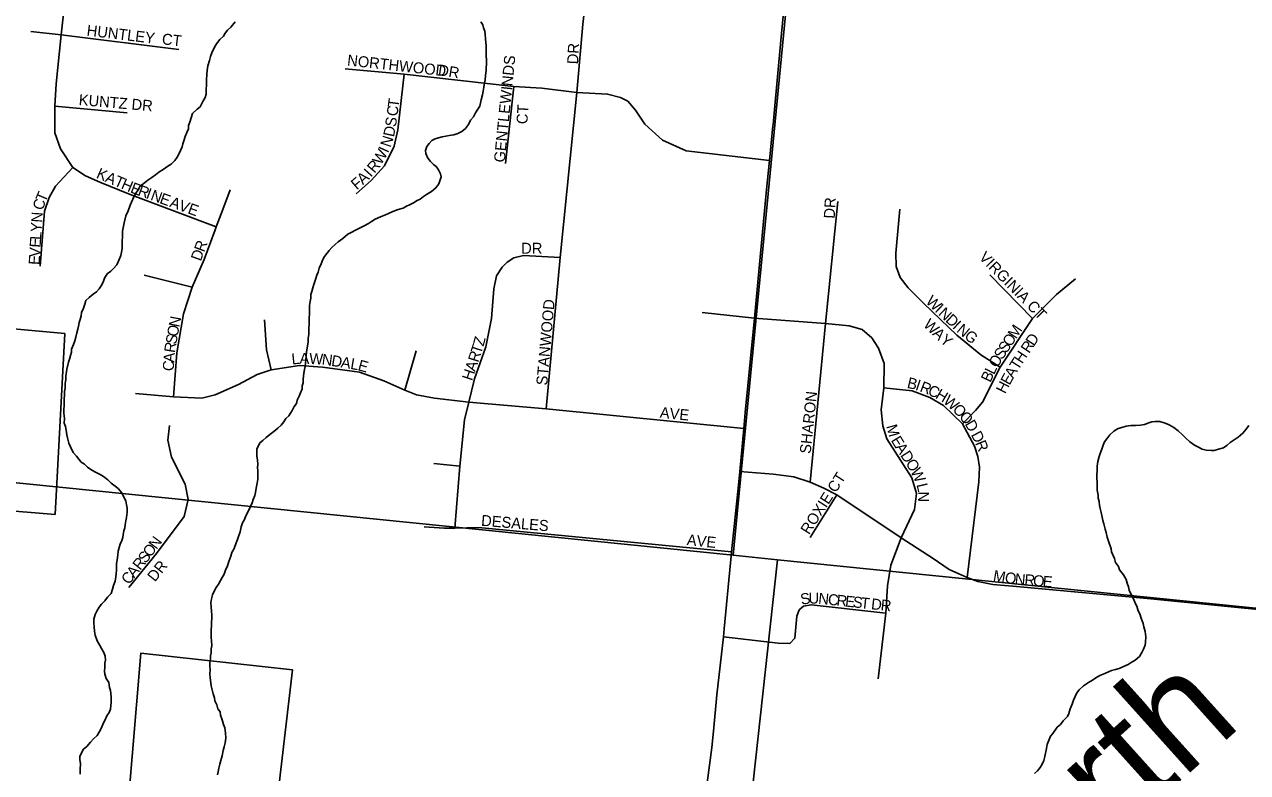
# Model space of a CAD drawing. Extents: x 0 to 1064, y 0 to 440.
# Drawn here: x 235.6 to 252.5, y 251.21 to 261.54 of the extents above; entities that cross this region are included whole.
import ezdxf

# ---------------------------------------------------------------- set-up
doc = ezdxf.new("R2010")
doc.units = 0
for name, color, linetype in [('GM_X_City_Street', 7, 'Continuous'), ('GM_X_City_Street_Text', 7, 'Continuous'), ('GM_X_Corporation', 7, 'Continuous'), ('GM_X_Minor_River', 7, 'Continuous'), ('GM_X_Minor_River_Text', 7, 'Continuous'), ('GM_X_Section', 7, 'Continuous'), ('GM_X_State_Route', 7, 'Continuous')]:
    doc.layers.add(name, color=color, linetype=linetype)

msp = doc.modelspace()

# ---------------------------------------------------------------- linework, layer by layer
at = {"layer": 'GM_X_City_Street'}
for points in [[(238.235, 258.707), (238.25, 258.748), (237.06, 259.196), (236.641, 259.365), (236.441, 259.452), (236.269, 259.569), (236.095, 259.825), (236.019, 260.045), (236.019, 260.414), (236.039, 260.725), (236.108, 261.4), (236.204, 262.278), (236.297, 263.152), (236.367, 264.019), (236.44, 264.965)], [(242.808, 256.231), (243.002, 258.326), (243.231, 260.605), (243.316, 261.548), (243.392, 262.217)], [(235.689, 261.448), (236.108, 261.4), (237.731, 261.2)], [(240.029, 260.931), (240.846, 260.859), (242.363, 260.688), (242.747, 260.662), (243.231, 260.605), (243.656, 260.583), (243.834, 260.536), (243.934, 260.484), (244.042, 260.358), (244.171, 260.165), (244.416, 259.943), (244.743, 259.798), (245.894, 259.666)], [(240.181, 259.202), (240.39, 259.387), (240.572, 259.589), (240.708, 259.863), (240.757, 260.086), (240.846, 260.859)], [(242.244, 259.623), (242.363, 260.688)], [(236.019, 260.414), (237.018, 260.325)], [(235.817, 258.206), (235.878, 258.963), (235.939, 259.152), (236.03, 259.309), (236.269, 259.569)], [(238.25, 258.748), (238.341, 258.987), (238.443, 259.259)], [(246.456, 255.22), (246.666, 257.413), (246.839, 259.097)], [(249.081, 256.809), (248.814, 256.979), (248.48, 257.251), (248.027, 257.686), (247.808, 257.907), (247.699, 258.046), (247.645, 258.2), (247.639, 258.383), (247.694, 258.99)], [(237.66, 256.398), (237.703, 257.006), (237.798, 257.545), (237.916, 257.914), (238.081, 258.296), (238.235, 258.707)], [(241.547, 254.586), (241.616, 255.442), (241.681, 256.081), (241.74, 256.326), (241.816, 256.649), (241.974, 257.088), (242.054, 257.482), (242.085, 257.89), (242.122, 258.072), (242.198, 258.191), (242.27, 258.261), (242.359, 258.321), (242.493, 258.35), (243.002, 258.326)], [(237.252, 258.08), (237.916, 257.914)], [(249.526, 257.48), (248.936, 258.085)], [(248.558, 256.027), (248.74, 256.209), (248.838, 256.326), (249.081, 256.809), (249.526, 257.48), (249.858, 257.814), (250.122, 258.027)], [(245.74, 257.482), (245.686, 257.486), (244.961, 257.563)], [(239.01, 256.771), (238.945, 257.049), (238.915, 257.464)], [(247.394, 252.503), (247.499, 253.409), (247.526, 253.785), (247.571, 254.074), (247.712, 254.449), (247.898, 254.844), (247.923, 255.064), (247.862, 255.278), (247.513, 255.82), (247.461, 256), (247.436, 256.22), (247.473, 256.524), (247.479, 256.86), (247.398, 257.069), (247.309, 257.213), (247.172, 257.329), (246.992, 257.38), (246.666, 257.413), (245.74, 257.482)], [(240.855, 256.491), (241.011, 257.036)], [(237.66, 256.398), (238.05, 256.38), (238.234, 256.425), (238.559, 256.571), (238.813, 256.706), (239.01, 256.771), (239.399, 256.832), (239.719, 256.81), (240.227, 256.739), (240.566, 256.622), (240.855, 256.491), (241.015, 256.428), (241.264, 256.381), (241.74, 256.326), (242.808, 256.231), (245.537, 255.959)], [(237.133, 256.446), (237.66, 256.398)], [(248.625, 253.903), (248.785, 255.223), (248.794, 255.429), (248.77, 255.575), (248.728, 255.716), (248.558, 256.027), (248.298, 256.278), (248.111, 256.391), (247.864, 256.48), (247.473, 256.524)], [(237.043, 253.765), (237.426, 254.234), (237.804, 254.743), (237.86, 254.981), (237.821, 255.194), (237.63, 255.564), (237.582, 255.798), (237.604, 256.002)], [(241.256, 255.477), (241.616, 255.442)], [(245.484, 255.365), (245.944, 255.328), (246.228, 255.291), (246.456, 255.22), (246.643, 255.137), (246.825, 255.046), (247.712, 254.449), (248.155, 254.163), (248.374, 254.011), (248.625, 253.903), (248.773, 253.849), (248.981, 253.805), (249.198, 253.786)], [(246.455, 254.455), (246.825, 255.046)], [(241.122, 254.601), (241.398, 254.584), (241.547, 254.586), (241.873, 254.595), (245.369, 254.259)], [(249.198, 253.786), (249.256, 253.781), (251.164, 253.606), (252.923, 253.434), (254.033, 253.283), (257.105, 252.989), (258.422, 252.857), (259.76, 252.73)], [(245.256, 253.082), (246.011, 252.993), (246.176, 252.99), (246.244, 253.064), (246.27, 253.37), (246.302, 253.455), (246.365, 253.507), (246.467, 253.525), (247.499, 253.409)]]:
    msp.add_lwpolyline(points, dxfattribs=at)
at = {"layer": 'GM_X_Corporation'}
msp.add_lwpolyline([(229.017, 255.354), (236.023, 254.775), (236.156, 257.273), (234.842, 257.395)], dxfattribs=at)
msp.add_lwpolyline([(236.902, 249.23), (239.076, 248.99), (239.161, 249.674), (238.956, 249.674), (239.304, 252.625), (237.209, 252.859)], close=True, dxfattribs=at)
at = {"layer": 'GM_X_Minor_River'}
for points in [[(236.222, 256.918), (236.236, 256.972), (236.249, 257.014), (236.251, 257.057), (236.277, 257.123), (236.297, 257.171), (236.311, 257.225), (236.325, 257.285), (236.339, 257.333), (236.346, 257.376), (236.354, 257.424), (236.368, 257.466), (236.382, 257.52), (236.389, 257.563), (236.415, 257.623), (236.435, 257.677), (236.449, 257.731), (236.493, 257.772), (236.55, 257.819), (236.593, 257.848), (236.631, 257.889), (236.657, 257.931), (236.689, 257.984), (236.703, 258.039), (236.742, 258.098), (236.791, 258.133), (236.829, 258.174), (236.874, 258.222), (236.906, 258.294), (236.933, 258.353), (236.94, 258.396), (236.948, 258.45), (236.95, 258.499), (236.951, 258.547), (236.954, 258.62), (236.956, 258.687), (236.963, 258.735), (236.978, 258.801), (236.999, 258.898), (237.032, 258.97), (237.059, 259.048), (237.098, 259.132), (237.131, 259.197), (237.169, 259.257), (237.195, 259.305), (237.258, 259.357), (237.302, 259.393), (237.358, 259.427), (237.408, 259.468), (237.458, 259.503), (237.514, 259.538), (237.582, 259.584), (237.626, 259.613), (237.676, 259.666), (237.708, 259.708), (237.734, 259.75), (237.754, 259.804), (237.78, 259.851), (237.787, 259.894), (237.801, 259.936), (237.821, 259.996), (237.841, 260.05), (237.867, 260.104), (237.868, 260.146), (237.882, 260.194), (237.902, 260.254), (237.923, 260.315), (237.986, 260.373), (238.029, 260.408), (238.062, 260.48), (238.094, 260.534), (238.108, 260.582), (238.11, 260.631), (238.113, 260.722), (238.115, 260.776), (238.117, 260.855), (238.125, 260.909), (238.133, 260.97), (238.154, 261.048), (238.168, 261.102), (238.188, 261.15), (238.227, 261.228), (238.253, 261.276), (238.297, 261.335), (238.348, 261.382), (238.373, 261.424), (238.405, 261.465), (238.449, 261.507), (238.512, 261.578)], [(241.806, 260.267), (241.832, 260.321), (241.864, 260.375), (241.89, 260.417), (241.911, 260.501), (241.926, 260.573), (241.939, 260.621), (241.947, 260.676), (241.955, 260.736), (241.963, 260.779), (241.971, 260.839), (241.979, 260.906), (241.981, 260.948), (241.982, 260.991), (241.984, 261.051), (241.98, 261.112), (241.981, 261.155), (241.977, 261.209), (241.978, 261.252), (241.974, 261.294), (241.969, 261.343), (241.965, 261.41), (241.961, 261.453), (241.944, 261.496), (241.933, 261.539), (241.904, 261.582)], [(239.101, 255.967), (239.145, 256.008), (239.183, 256.055), (239.209, 256.097), (239.253, 256.138), (239.298, 256.21), (239.324, 256.263), (239.356, 256.305), (239.369, 256.353), (239.396, 256.407), (239.415, 256.455), (239.435, 256.509), (239.437, 256.551), (239.45, 256.593), (239.452, 256.642), (239.461, 256.727), (239.469, 256.775), (239.476, 256.817), (239.484, 256.866), (239.485, 256.908), (239.493, 256.963), (239.495, 257.017), (239.51, 257.102), (239.518, 257.156), (239.519, 257.205), (239.527, 257.265), (239.53, 257.338), (239.532, 257.417), (239.535, 257.49), (239.536, 257.544), (239.539, 257.611), (239.54, 257.659), (239.548, 257.714), (239.556, 257.762), (239.557, 257.811), (239.571, 257.853), (239.585, 257.907), (239.599, 257.949), (239.612, 257.991), (239.626, 258.033), (239.639, 258.081), (239.659, 258.123), (239.673, 258.178), (239.699, 258.238), (239.72, 258.298), (239.745, 258.339), (239.777, 258.381), (239.809, 258.422), (239.847, 258.464), (239.891, 258.505), (239.935, 258.54), (239.997, 258.587), (240.066, 258.645), (240.122, 258.674), (240.165, 258.697), (240.221, 258.725), (240.295, 258.76), (240.351, 258.794), (240.394, 258.823), (240.444, 258.852), (240.518, 258.886), (240.586, 258.915), (240.629, 258.931), (240.691, 258.96), (240.765, 258.988), (240.833, 259.004), (240.876, 259.033), (240.92, 259.05), (240.975, 259.079), (241.025, 259.113), (241.068, 259.13), (241.112, 259.165), (241.156, 259.194), (241.224, 259.235), (241.281, 259.288), (241.325, 259.341), (241.345, 259.395), (241.359, 259.437), (241.348, 259.48), (241.319, 259.535), (241.29, 259.579), (241.249, 259.611), (241.207, 259.654), (241.166, 259.704), (241.144, 259.76), (241.139, 259.802), (241.159, 259.856), (241.191, 259.898), (241.229, 259.939), (241.272, 259.962), (241.322, 259.979), (241.371, 259.989), (241.42, 260), (241.469, 260.011), (241.53, 260.021), (241.585, 260.037), (241.641, 260.066), (241.691, 260.107), (241.735, 260.16), (241.762, 260.22), (241.806, 260.267)], [(236.51, 251.626), (236.555, 251.673), (236.605, 251.72), (236.637, 251.774), (236.657, 251.815), (236.69, 251.893), (236.715, 251.935), (236.736, 251.989), (236.768, 252.037), (236.787, 252.085), (236.795, 252.133), (236.796, 252.176), (236.799, 252.254), (236.79, 252.34), (236.773, 252.383), (236.763, 252.45), (236.728, 252.506), (236.712, 252.567), (236.707, 252.609), (236.709, 252.664), (236.711, 252.719), (236.718, 252.761), (236.714, 252.816), (236.697, 252.865), (236.663, 252.921), (236.634, 252.97), (236.605, 253.026), (236.577, 253.105), (236.567, 253.16), (236.563, 253.221), (236.559, 253.276), (236.56, 253.325), (236.575, 253.391), (236.6, 253.439), (236.633, 253.492), (236.665, 253.534), (236.709, 253.581), (236.747, 253.629), (236.797, 253.682), (236.817, 253.742), (236.831, 253.79), (236.851, 253.85), (236.86, 253.91), (236.867, 253.953), (236.869, 254.007), (236.87, 254.05), (236.872, 254.098), (236.88, 254.147), (236.888, 254.213), (236.896, 254.268), (236.909, 254.316), (236.923, 254.364), (236.943, 254.412), (236.957, 254.454), (236.964, 254.496), (236.972, 254.545), (236.985, 254.587), (236.993, 254.629), (237.001, 254.683), (237.008, 254.732), (237.017, 254.804), (237.019, 254.865), (237.008, 254.908), (236.998, 254.963), (236.963, 255.031), (236.947, 255.074), (236.894, 255.13), (236.852, 255.162), (236.799, 255.206), (236.751, 255.25), (236.692, 255.3), (236.644, 255.326), (236.59, 255.352), (236.53, 255.384), (236.471, 255.429), (236.43, 255.466), (236.382, 255.498), (236.318, 255.579), (236.271, 255.629), (236.237, 255.709), (236.214, 255.758), (236.192, 255.832), (236.187, 255.875), (236.177, 255.936), (236.167, 255.991), (236.15, 256.034), (236.152, 256.1), (236.142, 256.174), (236.144, 256.222), (236.146, 256.277), (236.147, 256.319), (236.149, 256.368), (236.151, 256.422), (236.152, 256.471), (236.16, 256.519), (236.162, 256.586), (236.17, 256.634), (236.171, 256.683), (236.187, 256.779), (236.208, 256.876), (236.222, 256.918)], [(251.083, 253.155), (251.067, 253.222), (251.056, 253.265), (251.028, 253.339), (251.012, 253.4), (250.989, 253.443), (250.967, 253.505), (250.944, 253.548), (250.927, 253.597), (250.893, 253.659), (250.864, 253.727), (250.854, 253.775), (250.837, 253.825), (250.82, 253.874), (250.786, 253.941), (250.728, 254.01), (250.717, 254.053), (250.676, 254.109), (250.66, 254.164), (250.62, 254.256), (250.615, 254.299), (250.576, 254.403), (250.56, 254.459), (250.544, 254.526), (250.533, 254.569), (250.511, 254.642), (250.5, 254.691), (250.49, 254.734), (250.474, 254.801), (250.463, 254.856), (250.452, 254.899), (250.448, 254.954), (250.437, 254.997), (250.433, 255.039), (250.423, 255.107), (250.419, 255.173), (250.42, 255.216), (250.416, 255.277), (250.418, 255.325), (250.419, 255.374), (250.421, 255.441), (250.43, 255.507), (250.45, 255.573), (250.464, 255.615), (250.484, 255.675), (250.504, 255.73), (250.524, 255.777), (250.556, 255.819), (250.594, 255.872), (250.651, 255.925), (250.713, 255.96), (250.762, 255.977), (250.823, 255.993), (250.884, 256.003), (250.951, 256.001), (251.018, 256.005), (251.074, 256.016), (251.135, 256.038), (251.178, 256.055), (251.221, 256.06), (251.288, 256.057), (251.361, 256.037), (251.414, 256.011), (251.48, 255.973), (251.54, 255.928), (251.599, 255.872), (251.646, 255.828), (251.699, 255.778), (251.765, 255.733), (251.812, 255.707), (251.872, 255.675), (251.927, 255.661), (251.994, 255.659), (252.036, 255.658), (252.098, 255.674), (252.165, 255.696), (252.215, 255.731), (252.259, 255.766), (252.302, 255.795), (252.371, 255.842), (252.434, 255.895), (252.478, 255.954), (252.516, 256.001)], [(238.268, 251.177), (238.275, 251.219), (238.283, 251.267), (238.297, 251.321), (238.311, 251.376), (238.331, 251.436), (238.346, 251.514), (238.359, 251.562), (238.373, 251.617), (238.382, 251.683), (238.378, 251.756), (238.368, 251.823), (238.351, 251.872), (238.329, 251.934), (238.307, 252.001), (238.302, 252.044), (238.273, 252.087), (238.257, 252.142), (238.228, 252.198), (238.223, 252.241), (238.207, 252.296), (238.191, 252.351), (238.18, 252.406), (238.175, 252.449), (238.165, 252.516), (238.161, 252.571), (238.163, 252.625), (238.159, 252.68), (238.16, 252.722), (238.168, 252.777), (238.169, 252.819), (238.177, 252.862), (238.179, 252.916), (238.186, 252.965), (238.182, 253.025), (238.178, 253.074), (238.18, 253.129), (238.181, 253.177), (238.183, 253.238), (238.185, 253.286), (238.186, 253.335), (238.188, 253.384), (238.184, 253.438), (238.18, 253.499), (238.175, 253.554), (238.183, 253.608), (238.197, 253.663), (238.223, 253.723), (238.249, 253.764), (238.281, 253.812), (238.307, 253.86), (238.333, 253.901), (238.359, 253.949), (238.379, 254.003), (238.405, 254.063), (238.425, 254.123), (238.452, 254.195), (238.466, 254.249), (238.498, 254.303), (238.525, 254.381), (238.545, 254.429), (238.559, 254.471), (238.579, 254.531), (238.593, 254.604), (238.613, 254.658), (238.639, 254.706), (238.659, 254.754), (238.692, 254.813), (238.724, 254.885), (238.744, 254.933), (238.758, 254.981), (238.784, 255.035), (238.792, 255.077), (238.8, 255.138), (238.814, 255.204), (238.822, 255.259), (238.824, 255.332), (238.826, 255.374), (238.821, 255.423), (238.823, 255.465), (238.819, 255.526), (238.808, 255.581), (238.81, 255.623), (238.811, 255.678), (238.831, 255.72), (238.851, 255.762), (238.894, 255.797), (238.938, 255.838), (238.988, 255.879), (239.045, 255.92), (239.101, 255.967)], [(249.557, 251.192), (249.595, 251.233), (249.633, 251.275), (249.659, 251.322), (249.685, 251.376), (249.699, 251.431), (249.721, 251.539), (249.729, 251.594), (249.748, 251.642), (249.775, 251.708), (249.807, 251.749), (249.87, 251.832), (249.914, 251.873), (249.953, 251.921), (250.009, 251.98), (250.029, 252.022), (250.049, 252.088), (250.076, 252.154), (250.096, 252.208), (250.116, 252.256), (250.142, 252.31), (250.174, 252.351), (250.23, 252.404), (250.299, 252.45), (250.355, 252.485), (250.404, 252.514), (250.46, 252.549), (250.528, 252.577), (250.578, 252.6), (250.621, 252.617), (250.676, 252.633), (250.725, 252.644), (250.775, 252.667), (250.849, 252.701), (250.892, 252.73), (250.948, 252.758), (251.005, 252.811), (251.037, 252.865), (251.063, 252.913), (251.083, 252.967), (251.09, 253.009), (251.093, 253.082), (251.083, 253.155)], [(236.368, 251.187), (236.37, 251.253), (236.373, 251.326), (236.363, 251.387), (236.364, 251.43), (236.39, 251.49), (236.416, 251.531), (236.46, 251.566), (236.51, 251.626)]]:
    msp.add_lwpolyline(points, dxfattribs=at)
at = {"layer": 'GM_X_Section'}
for points in [[(247.278, 273.713), (245.391, 254.213), (229.691, 255.797), (228.85, 255.88), (230.695, 275.436)], [(264.038, 272.108), (262.096, 252.537), (261.545, 252.577), (246.002, 254.147), (245.391, 254.213), (247.278, 273.713)], [(229.691, 255.797), (245.391, 254.213), (246.002, 254.147), (244.181, 237.481), (227.888, 239.125)], [(246.002, 254.147), (261.545, 252.577), (259.813, 235.795), (244.181, 237.481)]]:
    msp.add_lwpolyline(points, close=True, dxfattribs=at)
at = {"layer": 'GM_X_State_Route'}
for points in [[(245.943, 260.162), (245.958, 260.32), (246.048, 261.321), (246.161, 262.48), (246.293, 263.96)], [(245.576, 256.366), (245.66, 257.208), (245.686, 257.486), (245.75, 258.179), (245.854, 259.265), (245.894, 259.666), (245.941, 260.144), (245.943, 260.162)], [(245.358, 254.152), (245.369, 254.259), (245.467, 255.176), (245.484, 255.365), (245.537, 255.959), (245.557, 256.183), (245.572, 256.325), (245.576, 256.366)], [(245.119, 251.781), (245.168, 252.283), (245.256, 253.082), (245.269, 253.193), (245.353, 254.103), (245.358, 254.151), (245.358, 254.152)], [(242.591, 244.108), (242.6, 244.173), (242.632, 244.35), (242.69, 244.506), (242.928, 245.112), (243.255, 245.992), (243.577, 246.852), (243.937, 247.809), (244.251, 248.717), (244.517, 249.416), (244.757, 250.061), (244.914, 250.495), (244.981, 250.792), (245.03, 251.064), (245.097, 251.555), (245.119, 251.781)]]:
    msp.add_lwpolyline(points, dxfattribs=at)

# ---------------------------------------------------------------- texts
at = {"layer": 'GM_X_City_Street_Text'}
for s, height, rotation, p in [('HUNTLEY', 0.1515, 353.0891, (236.453, 261.391)), ('CT', 0.1515, 353.6638, (237.493, 261.271)), ('DR', 0.1515, 86.9884, (243.248, 260.991)), ('NORTHWOOD', 0.1515, 353.6609, (240.053, 260.978)), ('GENTLEWINDS', 0.15152, 84.2903, (242.235, 259.632)), ('DR', 0.1515, 351.0215, (241.307, 260.844)), ('KUNTZ DR', 0.1515, 355.1036, (236.345, 260.431)), ('C', 0.152, 82.4984, (240.752, 260.269)), ('T', 0.152, 82.492, (240.768, 260.388)), ('CT', 0.1515, 86.8222, (242.548, 260.163)), ('S', 0.152, 81.8363, (240.731, 260.122)), ('D', 0.152, 78.43, (240.703, 259.982)), ('N', 0.152, 71.6713, (240.656, 259.836)), ('W', 0.152, 59.8449, (240.527, 259.594)), ('I', 0.152, 65.6406, (240.622, 259.759)), ('R', 0.152, 50.2974, (240.435, 259.48)), ('K', 0.152, 336.6522, (236.581, 259.429)), ('A', 0.152, 336.6235, (236.703, 259.376)), ('T', 0.152, 336.6657, (236.826, 259.323)), ('H', 0.152, 336.8706, (236.924, 259.281)), ('F', 0.152, 40.7465, (240.191, 259.251)), ('A', 0.152, 42.0057, (240.275, 259.323)), ('I', 0.152, 48.1048, (240.386, 259.425)), ('T', 0.152, 66.7727, (235.887, 259.077)), ('E', 0.152, 338.9215, (237.052, 259.226)), ('R', 0.152, 340.0053, (237.155, 259.187)), ('I', 0.152, 340.0758, (237.268, 259.146)), ('N', 0.152, 340.0903, (237.331, 259.123)), ('C', 0.152, 72.9705, (235.854, 258.967)), ('E', 0.152, 340.0963, (237.456, 259.078)), ('A', 0.152, 340.0903, (237.594, 259.028)), ('V', 0.152, 340.0785, (237.719, 258.982)), ('E', 0.152, 340.0859, (237.845, 258.937)), ('DR', 0.1515, 86.8215, (246.794, 258.858)), ('N', 0.152, 86.5232, (235.843, 258.803)), ('Y', 0.152, 86.5473, (235.835, 258.67)), ('E', 0.152, 86.5276, (235.822, 258.457)), ('L', 0.152, 86.5455, (235.829, 258.564)), ('V', 0.152, 86.5473, (235.814, 258.324)), ('D', 0.152, 70.086, (238.036, 258.264)), ('R', 0.152, 69.5065, (238.081, 258.389)), ('DR', 0.1515, 0, (242.463, 258.376)), ('VIRGINIA CT', 0.15152, 314.517, (248.777, 258.316)), ('E', 0.152, 86.5276, (235.808, 258.218)), ('STANWOOD', 0.1515, 84.9363, (242.821, 256.552)), ('W', 0.152, 316.7717, (248.042, 257.704)), ('I', 0.152, 316.7619, (248.169, 257.585)), ('N', 0.152, 316.7619, (248.217, 257.539)), ('D', 0.152, 316.7842, (248.315, 257.448)), ('O', 0.152, 79.2944, (237.715, 257.222)), ('N', 0.152, 79.2832, (237.74, 257.353)), ('W', 0.152, 316.272, (248.009, 257.382)), ('I', 0.152, 316.9801, (248.412, 257.356)), ('N', 0.152, 320.0942, (248.468, 257.305)), ('M', 0.152, 56.3049, (249.3, 257.19)), ('S', 0.152, 79.3384, (237.696, 257.117)), ('Z', 0.152, 75.0283, (241.942, 257.089)), ('A', 0.152, 316.5926, (248.135, 257.261)), ('Y', 0.152, 319.8375, (248.239, 257.164)), ('G', 0.152, 321.7807, (248.574, 257.216)), ('O', 0.152, 56.3186, (249.226, 257.079)), ('D', 0.152, 56.3099, (249.547, 257.09)), ('R', 0.152, 80.9049, (237.677, 257)), ('T', 0.152, 71.7622, (241.905, 256.979)), ('S', 0.152, 56.4539, (249.108, 256.902)), ('S', 0.152, 56.2948, (249.167, 256.991)), ('H', 0.152, 56.5464, (249.384, 256.846)), ('R', 0.152, 56.3065, (249.48, 256.99)), ('C', 0.152, 86.8417, (237.661, 256.751)), ('A', 0.152, 85.9097, (237.668, 256.87)), ('L', 0.152, 5.8574, (239.297, 256.844)), ('A', 0.152, 358.9071, (239.399, 256.855)), ('W', 0.152, 357.0058, (239.531, 256.853)), ('N', 0.152, 352.6581, (239.701, 256.844)), ('D', 0.152, 350.9796, (239.832, 256.827)), ('A', 0.152, 350.9365, (239.963, 256.806)), ('L', 0.152, 350.2817, (240.095, 256.785)), ('E', 0.152, 344.5125, (240.196, 256.768)), ('R', 0.152, 71.7493, (241.868, 256.865)), ('O', 0.152, 58.8263, (249.04, 256.789)), ('T', 0.152, 57.3633, (249.327, 256.756)), ('H', 0.152, 71.7516, (241.784, 256.611)), ('A', 0.152, 71.764, (241.826, 256.738)), ('B', 0.152, 64.6515, (248.944, 256.588)), ('L', 0.152, 63.9847, (248.995, 256.696)), ('E', 0.152, 61.2347, (249.21, 256.55)), ('A', 0.152, 59.6885, (249.261, 256.643)), ('B', 0.152, 346.5468, (247.785, 256.525)), ('I', 0.152, 340.9844, (247.898, 256.498)), ('R', 0.152, 339.2763, (247.96, 256.477)), ('C', 0.152, 335.1943, (248.069, 256.435)), ('H', 0.152, 63.2004, (249.15, 256.432)), ('SHARON', 0.1515, 83.9904, (246.461, 255.606)), ('H', 0.152, 329.3549, (248.175, 256.387)), ('W', 0.152, 319.5701, (248.284, 256.323)), ('AVE', 0.1515, 354.0903, (244.373, 256.111)), ('O', 0.152, 314.6754, (248.413, 256.213)), ('O', 0.152, 310.3595, (248.505, 256.12)), ('D', 0.152, 299.9591, (248.587, 256.025)), ('M', 0.152, 285.5826, (247.504, 255.994)), ('E', 0.152, 301.3295, (247.566, 255.799)), ('D', 0.152, 297.8359, (248.672, 255.875)), ('A', 0.152, 302.9399, (247.623, 255.703)), ('R', 0.152, 292.2388, (248.732, 255.761)), ('D', 0.152, 302.902, (247.696, 255.592)), ('O', 0.152, 302.902, (247.768, 255.48)), ('ROXIE CT', 0.1515, 57.3198, (246.439, 254.485)), ('W', 0.152, 295.2566, (247.838, 255.372)), ('L', 0.152, 283.1216, (247.923, 255.186)), ('N', 0.152, 269.5191, (247.946, 255.092)), ('DESALES', 0.1515, 355.2352, (241.905, 254.618)), ('O', 0.152, 52.3435, (237.34, 254.172)), ('N', 0.152, 53.8144, (237.424, 254.281)), ('AVE', 0.1515, 354.0903, (244.746, 254.351)), ('R', 0.152, 51.5942, (237.198, 253.993)), ('S', 0.152, 51.562, (237.273, 254.087)), ('A', 0.152, 51.5518, (237.115, 253.888)), ('DR', 0.1515, 51.3366, (237.402, 253.833)), ('M', 0.152, 350.0975, (248.975, 253.858)), ('C', 0.152, 51.5754, (237.041, 253.794)), ('O', 0.152, 352.5191, (249.139, 253.829)), ('N', 0.152, 354.7331, (249.278, 253.811)), ('R', 0.152, 354.8036, (249.411, 253.799)), ('O', 0.152, 354.7917, (249.53, 253.788)), ('E', 0.152, 354.7966, (249.663, 253.776)), ('S', 0.152, 10.3024, (246.335, 253.524)), ('U', 0.152, 359.2568, (246.432, 253.542)), ('N', 0.152, 354.1328, (246.562, 253.541)), ('C', 0.152, 353.9414, (246.695, 253.527)), ('R', 0.152, 353.9671, (246.814, 253.515)), ('E', 0.152, 353.9495, (246.933, 253.502)), ('S', 0.152, 353.9524, (247.039, 253.491)), ('T', 0.152, 353.957, (247.146, 253.479)), ('D', 0.152, 353.9784, (247.292, 253.464)), ('R', 0.152, 353.9414, (247.424, 253.45))]:
    msp.add_text(s, height=height, rotation=rotation, dxfattribs=at).set_placement(p)
at = {"layer": 'GM_X_Minor_River_Text'}
msp.add_text('North', height=1.5152, rotation=41.9759, dxfattribs=at).set_placement((248.756, 248.554))

doc.saveas('drawing.dxf')
